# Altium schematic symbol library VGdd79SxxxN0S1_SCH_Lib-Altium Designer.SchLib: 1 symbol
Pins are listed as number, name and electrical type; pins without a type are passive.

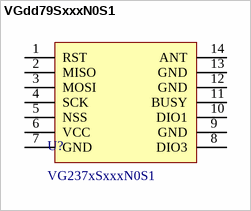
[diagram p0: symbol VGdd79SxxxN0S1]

## VGdd79SxxxN0S1
designator U?, comment VG237xSxxxN0S1
footprint G237xNS1
footprint G237xNS1-TO
pins: 1 RST, 2 MISO, 3 MOSI, 4 SCK, 5 NSS, 6 VCC, 7 GND, 8 DIO3, 9 GND, 10 DIO1, 11 BUSY, 12 GND, 13 GND, 14 ANT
